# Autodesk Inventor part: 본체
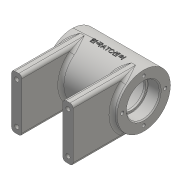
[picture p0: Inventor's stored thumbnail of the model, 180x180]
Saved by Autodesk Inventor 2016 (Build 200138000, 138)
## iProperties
Created: 2020-07
Part Number: 본체
Material: Generic
Document SubType Name: Modeling
Designer: user
Density: 1 g/cm^3
Appearance: Default
Author: user
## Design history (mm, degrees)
sketch "스케치1"
  geometry: L1 (-35, 0)-(35, 0); L2 (-35, 0)-(-35, 26); L3 (-35, 26)-(35, 26); L4 (35, 26)-(35, 0); L5 (-35, 16)-(-23, 16); L6 (-23, 16)-(-23, 14); L7 (-23, 14)-(-21, 14); L8 (-21, 14)-(-21, 21); L9 (-21, 21)-(21, 21); L10 (21, 21)-(21, 14); L11 (21, 14)-(23, 14); L12 (23, 14)-(23, 16); L13 (23, 16)-(35, 16); 2 further points
  constraints: 26 end point, 9 perpendicular, 3 horizontal, 2 horizontal alignment, 2 point on line, 1 coincident, 1 midpoint, 1 vertical
  dimensions: "d0" = 28 diameter of L11 L1; "d1" = 32 diameter of L13 L1; "d2" = 52 diameter of L3 L1; "d3" = 42 diameter of L9 L1; "d4" = 12 distance of L5.start L5.end; "d5" = 2 distance of L6.end L7.end; "d6" = 42 distance of L8.end L9.end; "d7" = 12 distance of L12.end L13.end; "d8" = 2 distance of L10.end L11.end
revolve "회전1" sketch "스케치1" stored, may be unused: angle "d9" = 90 deg
node "작업 평면1"
sketch "스케치2"
  geometry: L1 (0, -26)-(-64, -26); L2 (-64, -26)-(-64, 26); L3 (-64, 26)-(0, 26); A1 r 26 centre (0, 0) between (0, -26) and (0, 26) reference; A2 r 26 centre (0, 0) between (0, -26) and (0, 26) reference; 1 further point
  constraints: 6 end point, 4 point on circle, 2 tangent, 1 horizontal, 1 parallel, 1 perpendicular
  dimensions: "d11" = 64 distance from line of L2 point (0, 0)
extrude "돌출1" join sketch "스케치2" distance "d12" = 10; taper "d13" = 0 deg
node "작업 평면2"
sketch "스케치3"
  geometry: C1 r 5 at (0, 0); 1 further point
  constraints: 1 centre point, 1 coincident
  dimensions: "d15" = 10 diameter of C1
extrude "돌출2" join sketch "스케치3" stored distance "d16" = 10; taper "d17" = 0 deg
hole "구멍1" diameter "d20" = 5.188; stored, may be unused: countersink angle "d24" = 90 deg, drill point angle "d26" = 118 deg; dims "d18" = 10, "d19" = 10, "d21" = 12, "d22" = 4, "d23" = 2, "d25" = 16
sketch "스케치4"
  geometry: L1 (0, 0)-(0, 21)
  constraints: 2 end point, 1 vertical
  dimensions: "d27" = 21 distance of L1.start L1.end
hole "구멍2" sketch "스케치4" at (0, 21) diameter "d28" = 3.242; stored, may be unused: countersink angle "d32" = 90 deg, drill point angle "d34" = 118 deg; dims "d29" = 8, "d30" = 4, "d31" = 2, "d33" = 10
sketch "스케치5"
  geometry: L1 (-5, 6)-(45, 6); L2 (45, 6)-(45, 46); L3 (45, 46)-(-5, 46); L4 (-5, 46)-(-5, 6); L5 (-5, 6)-(45, 46); L6 (45, 6)-(-5, 46); L7 (-10, 0)-(-10, 52) reference; 1 further point
  constraints: 12 end point, 2 midpoint, 2 parallel, 1 horizontal, 1 perpendicular
  dimensions: "d39" = 40 distance of L1.end L2.end; "d40" = 5 distance between parallel lines of L7 L4
hole "구멍3" sketch "스케치5" at (-5, 46), (45, 46), (45, 6), (-5, 6) diameter "d41" = 4.134; stored, may be unused: countersink angle "d45" = 90 deg, drill point angle "d47" = 118 deg; dims "d42" = 8, "d43" = 4, "d44" = 2, "d46" = 10
sketch "스케치6"
  geometry: L1 (29, -5)-(25.515, -5) reference; L2 (25.515, 5)-(29, 5) reference; L3 (29, 5)-(29, 2.594) reference; L4 (29, 2.594)-(20.839, 2.594) reference; L5 (20.839, -2.594)-(29, -2.594) reference; L6 (29, -2.594)-(29, -5) reference; L7 (0, 0)-(-27.251, -9.919); L8 (-27.251, -9.919)-(-25.199, -15.557); L9 (-25.199, -15.557)-(-21.72, -14.291); L10 (0, 0)-(-26, 0); A1 r 26 centre (0, 0) between (25.515, 5) and (25.515, -5) reference; A2 r 21 centre (0, 0) between (20.839, 2.594) and (20.839, -2.594) reference; A3 r 26 centre (0, 0) between (0, 26) and (0, -26) reference; A4 r 26 centre (0, 0) between (-24.432, -8.893) and (-21.72, -14.291); 1 further point
  constraints: 8 end point, 6 point on circle, 1 centre point, 1 parallel, 1 perpendicular, 1 point on line
  dimensions: "d48" = 20 deg angle of L7 L10; "d49" = 29 distance from line of point (0, 0) L8; "d50" = 12 diameter of L9 L7
revolve "회전2" sketch "스케치6" stored, may be unused: angle "d51" = 90 deg
hole "구멍4" diameter "d54" = 5.188; stored, may be unused: countersink angle "d58" = 90 deg, drill point angle "d60" = 118 deg; dims "d52" = 10, "d53" = 10, "d55" = 12, "d56" = 4, "d57" = 2, "d59" = 16
fillet "모깎기1" dims "d61" = 2
fillet "모깎기2" dims "d62" = 3
fillet "모깎기3" dims "d63" = 3
fillet "모깎기4" dims "d64" = 3, "d65" = 0.3
chamfer "모따기1" distance "d66" = 1; stored, may be unused: second distance "d67" = 2, angle "d68" = 45 deg
sketch "스케치8"
  geometry: L1 (-35, -26)-(-35, 26) reference; L2 (-35, 26)-(35, 26) reference; 2 further points
  constraints: 1 other
  dimensions: "d74" = 35 distance from line of L1 point (0, 0); "d75" = 26 distance from line of L2 point (0, 0)
feature "엠보싱2" sketch "스케치8" dims "d0" = 28, "d1" = 32, "d2" = 52, "d3" = 42, "d4" = 12, "d5" = 2, "d6" = 42, "d7" = 12, "d8" = 2, "d11" = 64, "d76" = 0.5, "d77" = 0
node "솔리드1"
mirror "대칭1"
pattern_circular "원형 패턴1" dims angle "d36" = 360 deg
mirror "대칭2"
node "절단 모서리 투영1"
other parameters: "d14" = 29
